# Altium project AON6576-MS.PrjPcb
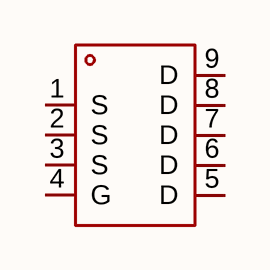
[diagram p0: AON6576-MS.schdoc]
1 sheet, 1 parts. Net scope: global (net labels, ports and power ports of the same name join across sheets).

## Sheet AON6576-MS.schdoc
size 127 x 101 mm

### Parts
Q?  aon6576-ms  [PDFN-8_L4.9-W5.8-P1.27-LS6.1-BL]  (value not drawn)

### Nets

Not connected (* = marked no-connect by the designer): Q? 1(S) 2(S) 3(S) 4(G) 5(D) 6(D) 7(D) 8(D) 9(D)

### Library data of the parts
Q? = aon6576-ms: 数量:1个N沟道;漏源电压(Vdss):30V;连续漏极电流(Id):60A;导通电阻(RDS(on)):4.4mΩ@10V;耗散功率(Pd):30W;阈值电压(Vgs(th)):1.2V;; Manufacturer: MSKSEMI(美森科); AddInBom: yes; ModelId: 178189b27e7544aca50c111426555358; ModelName: PDFN-8_L4.9-W5.8-H1.0-P1.27; ModelTransform: 200.787,240.157,0,0,0,0,-0.097,0,0; Number: 1个N沟道; Drain to Source Voltage: 30V; Current - Continuous Drain(Id): 60A; Pd - Power Dissipation: 30W; Gate Threshold Voltage (Vgs(th)): 1.2V; Gate Charge(Qg): 8nC; Input Capacitance(Ciss): 814pF; Reverse Transfer Capacitance (Crss@Vds): 41pF; Type: N沟道; Output Capacitance(Coss): 498pF; Vgs: ±20V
